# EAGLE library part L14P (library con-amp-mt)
AMP MT CONNECTOR
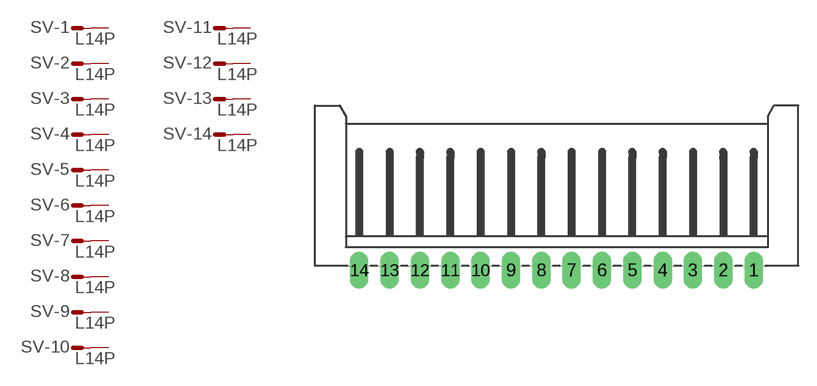
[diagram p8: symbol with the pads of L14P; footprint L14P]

Designator prefix SV; gates -1=M -2=M -3=M -4=M -5=M -6=M -7=M -8=M -9=M -10=M -11=M -12=M -13=M -14=M

## L14P (OC_FARNELL: unknown; OC_NEWARK: unknown)  [L14P]
1  -1:S  pas
2  -2:S  pas
3  -3:S  pas
4  -4:S  pas
5  -5:S  pas
6  -6:S  pas
7  -7:S  pas
8  -8:S  pas
9  -9:S  pas
10  -10:S  pas
11  -11:S  pas
12  -12:S  pas
13  -13:S  pas
14  -14:S  pas

## Footprint L14P (pad centres in mm)
AMP MT CONNECTOR
drill 1.016 long: 1 16.25,-6.25; 2 13.75,-6.25; 3 11.25,-6.25; 4 8.75,-6.25; 5 6.25,-6.25; 6 3.75,-6.25; 7 1.25,-6.25; 8 -1.25,-6.25; 9 -3.75,-6.25; 10 -6.25,-6.25; 11 -8.75,-6.25; 12 -11.25,-6.25; 13 -13.75,-6.25; 14 -16.25,-6.25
